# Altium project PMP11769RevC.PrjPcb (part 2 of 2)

## Sheet PMP11769RevC - Power Supply.SchDoc: Power Supply
size A3; Date: Not shown in title block; ApprovedBy: Not shown in title block; CheckedBy: Not shown in title block; Author: Not shown in title block; CompanyName: Not shown in title block; DrawnBy: Matthias Ulmann; Engineer: Matthias Ulmann; Organization: Not shown in title block; Address1: Not shown in title block; Address2: Not shown in title block; Address3: Not shown in title block; Address4: Not shown in title block; DocumentNumber: 4; Revision: Use project parameter SCH_Rev; SheetNumber: 4; SheetTotal: 4; PageSetup: Record=PageOptions¦CenterHorizontal=True¦CenterVertical=True¦PrintScale=0.96¦XCorrection=1.00¦YCorrection=1.00¦PrintKind=0¦BorderSize=5000000¦LeftOffset=0¦BottomOffset=0¦Orientation=2¦PaperLength=1000¦PaperWidth=1000¦Scale=100¦PaperSource=7¦PrintQuality=600¦MediaType=1¦DitherType=10¦PaperKind=11" x 17"¦PrintScaleMode=1
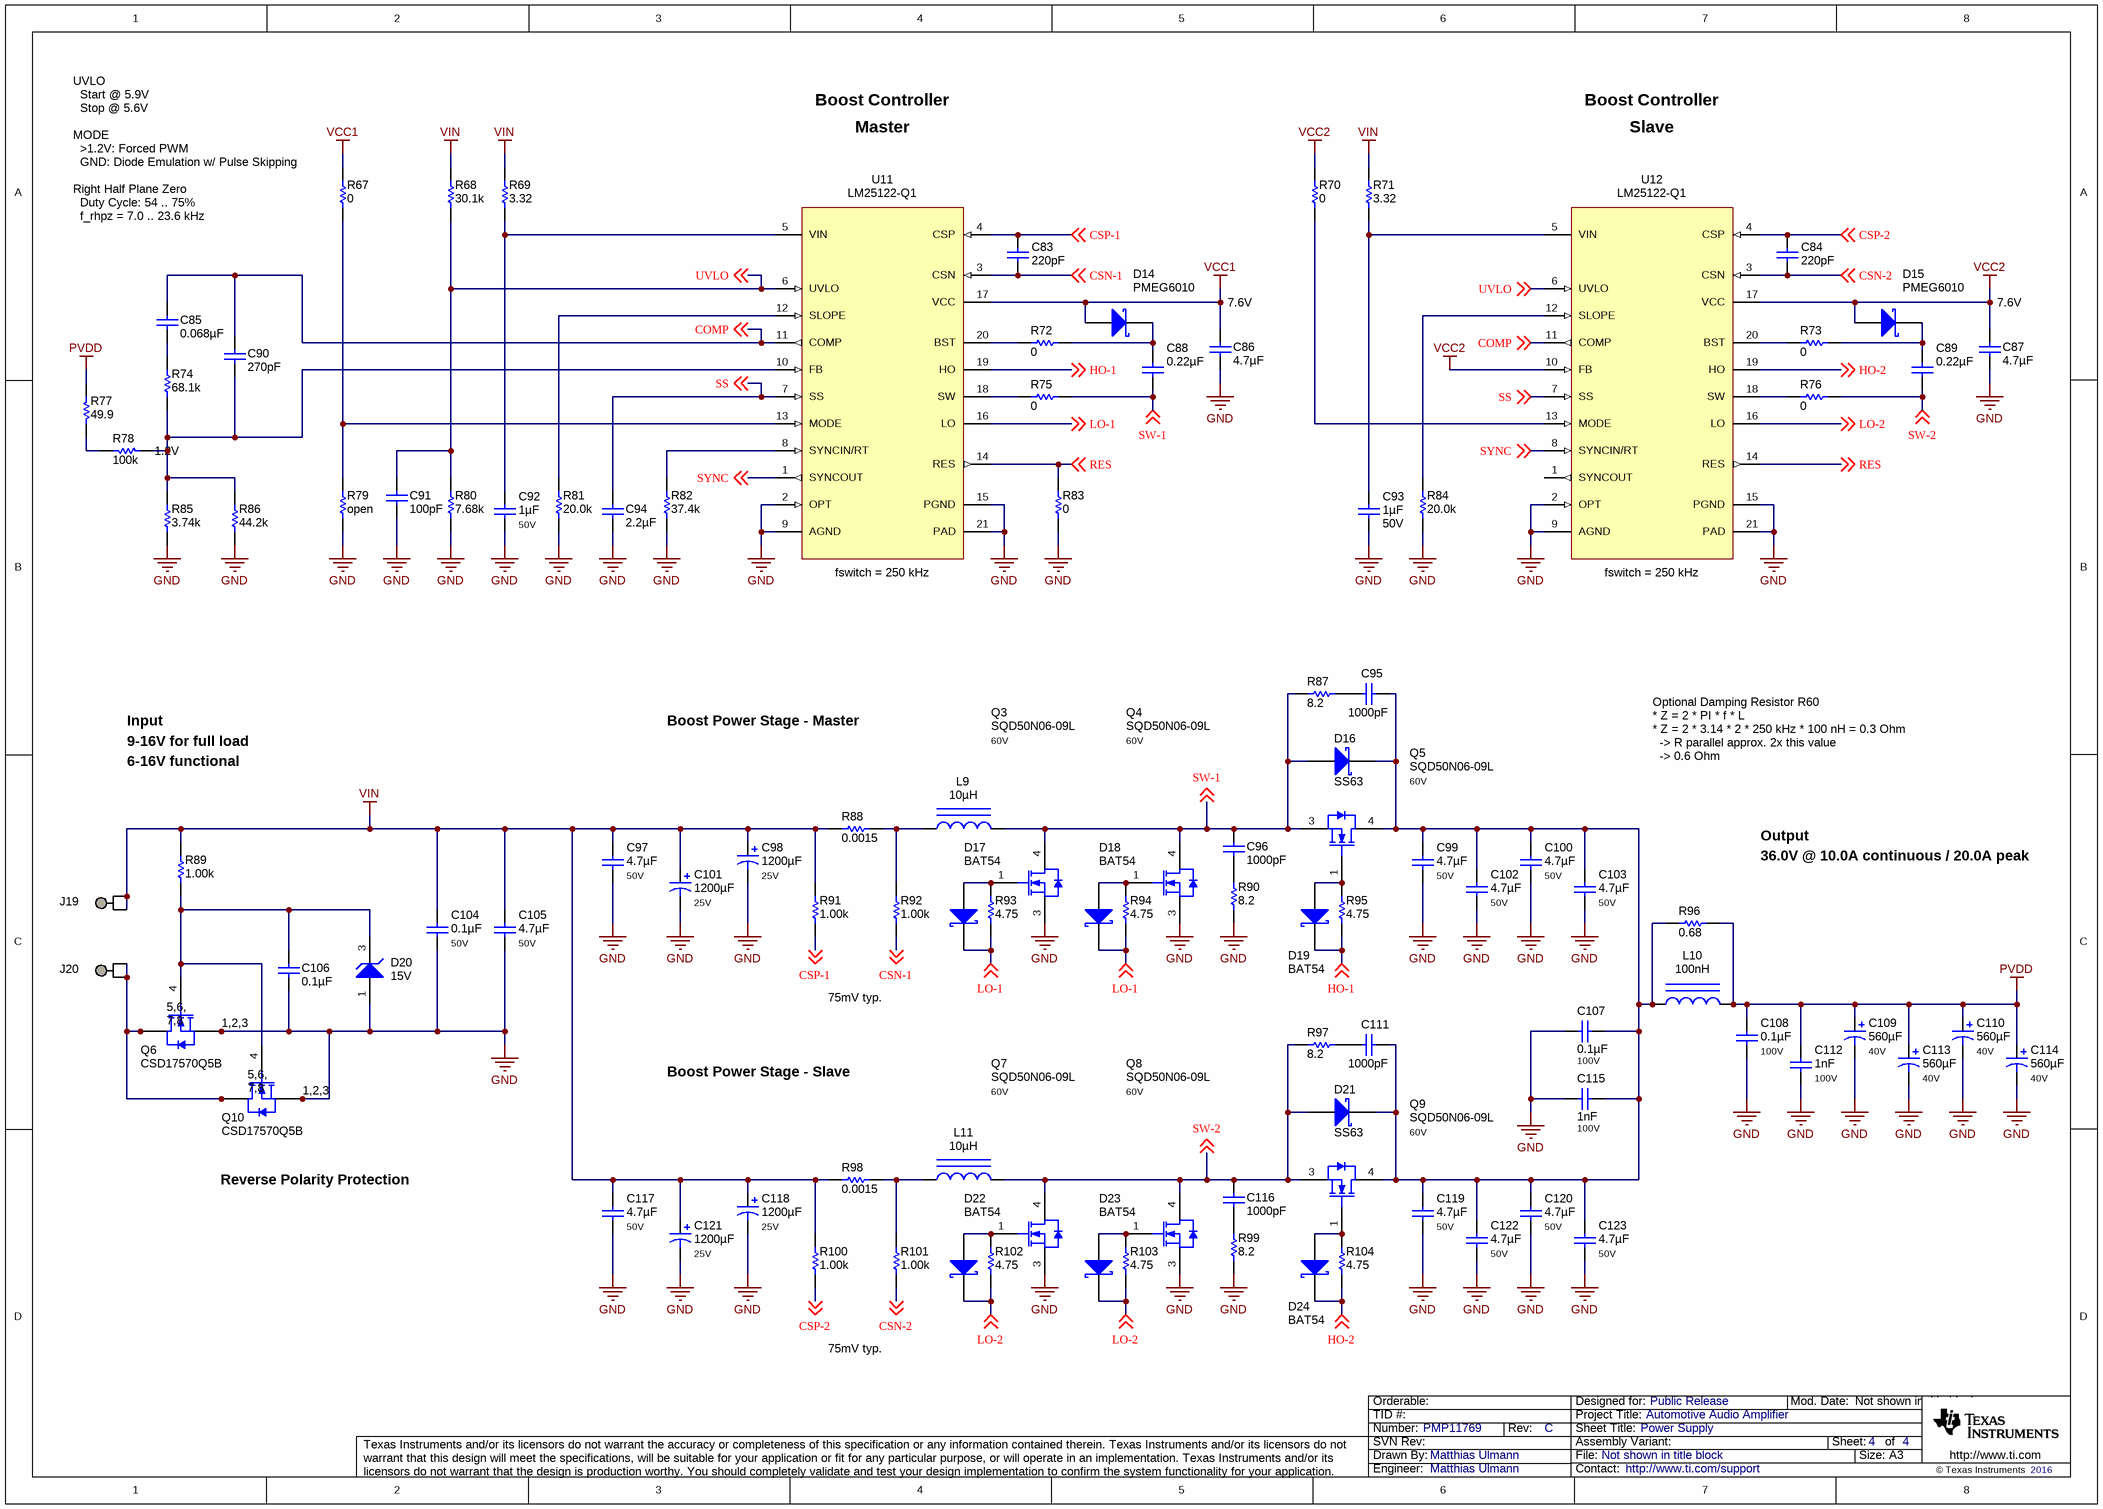
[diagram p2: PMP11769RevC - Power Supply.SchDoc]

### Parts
C83  ValueDisplayed: 220pF  [0603]  (hidden comment: C1608X7R1H221K)
C84  ValueDisplayed: 220pF  [0603]  (hidden comment: C1608X7R1H221K)
C85  ValueDisplayed: 0.068µF  [0603]  (hidden comment: C1608X7R1H683K080AA)
C86  ValueDisplayed: 4.7µF  [1206]  (hidden comment: C3216X7R1C475M)
C87  ValueDisplayed: 4.7µF  [1206]  (hidden comment: C3216X7R1C475M)
C88  ValueDisplayed: 0.22µF  [0805_HV]  (hidden comment: C2012X7R1E224K)
C89  ValueDisplayed: 0.22µF  [0805_HV]  (hidden comment: C2012X7R1E224K)
C90  ValueDisplayed: 270pF  [0603]  (hidden comment: GRM188R71H271KA01D)
C91  ValueDisplayed: 100pF  [0603]  (hidden comment: C1608C0G1H101J)
C92  ValueDisplayed: 1µF  Value2: 50V  [1206]  (hidden comment: C3216X7R1H105K)
C93  ValueDisplayed: 1µF  Value2: 50V  [1206]  (hidden comment: C3216X7R1H105K)
C94  ValueDisplayed: 2.2µF  [0603]  (hidden comment: GCM188R70J225KE22D)
C95  ValueDisplayed: 1000pF  [0805_HV]  (hidden comment: C2012X7R2A102M)
C96  ValueDisplayed: 1000pF  [0805_HV]  (hidden comment: C2012X7R2A102M)
C97  ValueDisplayed: 4.7µF  Value2: 50V  [1210]  (hidden comment: CGA6P3X7R1H475K250AB)
C98  ValueDisplayed: 1200µF  Value2: 25V  [PW_1800x2000]  (hidden comment: UPA1E122MHDANE)
C99  ValueDisplayed: 4.7µF  Value2: 50V  [1210]  (hidden comment: CGA6P3X7R1H475K250AB)
C100  ValueDisplayed: 4.7µF  Value2: 50V  [1210]  (hidden comment: CGA6P3X7R1H475K250AB)
C101  ValueDisplayed: 1200µF  Value2: 25V  [PW_1800x2000]  (hidden comment: UPA1E122MHDANE)
C102  ValueDisplayed: 4.7µF  Value2: 50V  [1210]  (hidden comment: CGA6P3X7R1H475K250AB)
C103  ValueDisplayed: 4.7µF  Value2: 50V  [1210]  (hidden comment: CGA6P3X7R1H475K250AB)
C104  ValueDisplayed: 0.1µF  Value2: 50V  [0603]  (hidden comment: C1608X7R1H104K)
C105  ValueDisplayed: 4.7µF  Value2: 50V  [1210]  (hidden comment: CGA6P3X7R1H475K250AB)
C106  ValueDisplayed: 0.1µF  [0603]  (hidden comment: C1608X7R1H104K)
C107  ValueDisplayed: 0.1µF  Value2: 100V  [0805_HV]  (hidden comment: C2012X7R2A104K125AA)
C108  ValueDisplayed: 0.1µF  Value2: 100V  [0805_HV]  (hidden comment: C2012X7R2A104K125AA)
C109  ValueDisplayed: 560µF  Value2: 40V  [PW_1800x2000]  (hidden comment: UPW1G561MHDANE)
C110  ValueDisplayed: 560µF  Value2: 40V  [PW_1800x2000]  (hidden comment: UPW1G561MHDANE)
C111  ValueDisplayed: 1000pF  [0805_HV]  (hidden comment: C2012X7R2A102M)
C112  ValueDisplayed: 1nF  Value2: 100V  [0805_HV]  (hidden comment: C2012X7R2A102M)
C113  ValueDisplayed: 560µF  Value2: 40V  [PW_1800x2000]  (hidden comment: UPW1G561MHDANE)
C114  ValueDisplayed: 560µF  Value2: 40V  [PW_1800x2000]  (hidden comment: UPW1G561MHDANE)
C115  ValueDisplayed: 1nF  Value2: 100V  [0805_HV]  (hidden comment: C2012X7R2A102M)
C116  ValueDisplayed: 1000pF  [0805_HV]  (hidden comment: C2012X7R2A102M)
C117  ValueDisplayed: 4.7µF  Value2: 50V  [1210]  (hidden comment: CGA6P3X7R1H475K250AB)
C118  ValueDisplayed: 1200µF  Value2: 25V  [PW_1800x2000]  (hidden comment: UPA1E122MHDANE)
C119  ValueDisplayed: 4.7µF  Value2: 50V  [1210]  (hidden comment: CGA6P3X7R1H475K250AB)
C120  ValueDisplayed: 4.7µF  Value2: 50V  [1210]  (hidden comment: CGA6P3X7R1H475K250AB)
C121  ValueDisplayed: 1200µF  Value2: 25V  [PW_1800x2000]  (hidden comment: UPA1E122MHDANE)
C122  ValueDisplayed: 4.7µF  Value2: 50V  [1210]  (hidden comment: CGA6P3X7R1H475K250AB)
C123  ValueDisplayed: 4.7µF  Value2: 50V  [1210]  (hidden comment: CGA6P3X7R1H475K250AB)
D14  PMEG6010  [SOD-123F]
D15  PMEG6010  [SOD-123F]
D16  SS63  [SMC]
D17  BAT54  [sod-323]
D18  BAT54  [sod-323]
D19  BAT54  [sod-323]
D20  value 15V  [SOT-23]  (hidden comment: BZX84C15LT1G)
D21  SS63  [SMC]
D22  BAT54  [sod-323]
D23  BAT54  [sod-323]
D24  BAT54  [sod-323]
J19  TESTPOINT_2Pos  [HIRSCHMANN_973 582-101]  (value not drawn)
J20  TESTPOINT_2Pos  [HIRSCHMANN_973 582-100]  (value not drawn)
L9  ValueDisplayed: 10µH  [SER2918H]  (hidden comment: SER2918H-103KL)
L10  100nH  [IHLP-2525AH]
L11  ValueDisplayed: 10µH  [SER2918H]  (hidden comment: SER2918H-103KL)
Q3  SQD50N06-09L  value 60V  [DPAK]
Q4  SQD50N06-09L  value 60V  [DPAK]
Q5  SQD50N06-09L  value 60V  [DPAK]
Q6  CSD17570Q5B  [TRANS_NexFET_Q5B]
Q7  SQD50N06-09L  value 60V  [DPAK]
Q8  SQD50N06-09L  value 60V  [DPAK]
Q9  SQD50N06-09L  value 60V  [DPAK]
Q10  CSD17570Q5B  [TRANS_NexFET_Q5B]
R67  ValueDisplayed: 0  [0603]  (hidden comment: CRCW06030000Z0EA)
R68  ValueDisplayed: 30.1k  [0603]  (hidden comment: CRCW060330K1FKEA)
R69  ValueDisplayed: 3.32  [0603]  (hidden comment: CRCW06033R32FKEA)
R70  ValueDisplayed: 0  [0603]  (hidden comment: CRCW06030000Z0EA)
R71  ValueDisplayed: 3.32  [0603]  (hidden comment: CRCW06033R32FKEA)
R72  ValueDisplayed: 0  [0603]  (hidden comment: CRCW06030000Z0EA)
R73  ValueDisplayed: 0  [0603]  (hidden comment: CRCW06030000Z0EA)
R74  ValueDisplayed: 68.1k  [0603]  (hidden comment: CRCW060368K1FKEA)
R75  ValueDisplayed: 0  [0603]  (hidden comment: CRCW06030000Z0EA)
R76  ValueDisplayed: 0  [0603]  (hidden comment: CRCW06030000Z0EA)
R77  ValueDisplayed: 49.9  [0603]  (hidden comment: CRCW060349R9FKEA)
R78  ValueDisplayed: 100k  [0603]  (hidden comment: CRCW0603100KFKEA)
R79  ValueDisplayed: open  [0603]  (hidden comment: CRCW06030000Z0EA)
R80  ValueDisplayed: 7.68k  [0603]  (hidden comment: CRCW06037K68FKEA)
R81  ValueDisplayed: 20.0k  [0603]  (hidden comment: CRCW060320K0FKEA)
R82  ValueDisplayed: 37.4k  [0603]  (hidden comment: CRCW060337K4FKEA)
R83  ValueDisplayed: 0  [0603]  (hidden comment: CRCW06030000Z0EA)
R84  ValueDisplayed: 20.0k  [0603]  (hidden comment: CRCW060320K0FKEA)
R85  ValueDisplayed: 3.74k  [0603]  (hidden comment: CRCW06033K74FKEA)
R86  ValueDisplayed: 44.2k  [0603]  (hidden comment: CRCW060344K2FKEA)
R87  ValueDisplayed: 8.2  [2010]  (hidden comment: CRCW20108R20JNEF)
R88  ValueDisplayed: 0.0015  [2512]  (hidden comment: ERJ-M1WTF1M5U)
R89  ValueDisplayed: 1.00k  [0603]  (hidden comment: CRCW06031K00FKEA)
R90  ValueDisplayed: 8.2  [2010]  (hidden comment: CRCW20108R20JNEF)
R91  ValueDisplayed: 1.00k  [0603]  (hidden comment: CRCW06031K00FKEA)
R92  ValueDisplayed: 1.00k  [0603]  (hidden comment: CRCW06031K00FKEA)
R93  ValueDisplayed: 4.75  [0603]  (hidden comment: CRCW06034R75FKEA)
R94  ValueDisplayed: 4.75  [0603]  (hidden comment: CRCW06034R75FKEA)
R95  ValueDisplayed: 4.75  [0603]  (hidden comment: CRCW06034R75FKEA)
R96  ValueDisplayed: 0.68  [2512]  (hidden comment: ERJ-1TRQJR68U)
R97  ValueDisplayed: 8.2  [2010]  (hidden comment: CRCW20108R20JNEF)
R98  ValueDisplayed: 0.0015  [2512]  (hidden comment: ERJ-M1WTF1M5U)
R99  ValueDisplayed: 8.2  [2010]  (hidden comment: CRCW20108R20JNEF)
R100  ValueDisplayed: 1.00k  [0603]  (hidden comment: CRCW06031K00FKEA)
R101  ValueDisplayed: 1.00k  [0603]  (hidden comment: CRCW06031K00FKEA)
R102  ValueDisplayed: 4.75  [0603]  (hidden comment: CRCW06034R75FKEA)
R103  ValueDisplayed: 4.75  [0603]  (hidden comment: CRCW06034R75FKEA)
R104  ValueDisplayed: 4.75  [0603]  (hidden comment: CRCW06034R75FKEA)
U11  LM25122-Q1  [PWP0020A_N]
U12  LM25122-Q1  [PWP0020A_N]

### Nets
GND: C86.2 C87.2 C91.2 C92.1 C93.1 C94.2 C97.2 C98.2(-) C99.2 C100.2 C101.2(-) C102.2 C103.2 C104.2 C105.2 C106.1 C107.1 C108.2 C109.2(-) C110.2(-) C112.2 C113.2(-) C114.2(-) C115.1 C117.2 C118.2(-) C119.2 C120.2 C121.2(-) C122.2 C123.2 D20.1(A) Q3.3(S) Q4.3(S) Q6.1(S) Q6.2(S) Q6.3(S) Q7.3(S) Q8.3(S) Q10.1(S) Q10.2(S) Q10.3(S) R79.2 R80.1 R81.1 R82.1 R83.1 R84.1 R85.1 R86.1 R90.1 R99.1 U11.2(OPT) U11.9(AGND) U11.15(PGND) U11.21(PAD) U12.2(OPT) U12.9(AGND) U12.15(PGND) U12.21(PAD)
PVDD: C108.1 C109.1(+) C110.1(+) C112.1 C113.1(+) C114.1(+) L10.2 R77.1 R96.2
VCC1: C86.1 D14.2(A) R67.1 U11.17(VCC)
VCC2: C87.1 D15.2(A) R70.1 U12.10(FB) U12.17(VCC)
VIN: C97.1 C98.1(+) C101.1(+) C104.1 C105.1 C117.1 C118.1(+) C121.1(+) J19.1 J19.2 R68.2 R69.2 R71.2 R88.1 R89.1 R91.2 R98.1 R100.2
COMP: C85.1 C90.1 U11.11(COMP) U12.11(COMP) ; off-sheet COMP
CSN-1: C83.2 R92.1 U11.3(CSN) ; off-sheet CSN-1
CSN-2: C84.2 R101.1 U12.3(CSN) ; off-sheet CSN-2
CSP-1: C83.1 R91.1 U11.4(CSP) ; off-sheet CSP-1
CSP-2: C84.1 R100.1 U12.4(CSP) ; off-sheet CSP-2
HO-1: D19.1(K) R95.1 U11.19(HO) ; off-sheet HO-1
HO-2: D24.1(K) R104.1 U12.19(HO) ; off-sheet HO-2
LO-1: D17.1(K) D18.1(K) R93.1 R94.1 U11.16(LO) ; off-sheet LO-1
LO-2: D22.1(K) D23.1(K) R102.1 R103.1 U12.16(LO) ; off-sheet LO-2
RES: R83.2 U11.14(RES) U12.14(RES) ; off-sheet RES
SS: C94.1 U11.7(SS) U12.7(SS) ; off-sheet SS
SW-1: C88.2 C96.1 D16.2(A) L9.1 Q3.4(D) Q4.4(D) Q5.3(S) R75.1 R87.1 ; off-sheet SW-1
SW-2: C89.2 C116.1 D21.2(A) L11.1 Q7.4(D) Q8.4(D) Q9.3(S) R76.1 R97.1 ; off-sheet SW-2
SYNC: U11.1(SYNCOUT) U12.8(SYNCIN/RT) ; off-sheet SYNC
UVLO: C91.1 R68.1 R80.2 U11.6(UVLO) U12.6(UVLO) ; off-sheet UVLO
NetC85_2: C85.2 R74.2
NetC88_1: C88.1 D14.1(K) R72.1
NetC89_1: C89.1 D15.1(K) R73.1
NetC90_2: C90.2 R74.1 R78.1 R85.2 R86.2 U11.10(FB)
NetC92_2: C92.2 R69.1 U11.5(VIN)
NetC93_2: C93.2 R71.1 U12.5(VIN)
NetC95_1: C95.1 R87.2
NetC95_2: C95.2 C99.1 C100.1 C102.1 C103.1 C107.2 C111.2 C115.2 C119.1 C120.1 C122.1 C123.1 D16.1(K) D21.1(K) L10.1 Q5.4(D) Q9.4(D) R96.1
NetC96_2: C96.2 R90.2
NetC106_2: C106.2 D20.3(K) Q6.4(G) Q10.4(G) R89.2
NetC111_1: C111.1 R97.2
NetC116_2: C116.2 R99.2
NetD17_2: D17.2(A) Q3.1(G) R93.2
NetD18_2: D18.2(A) Q4.1(G) R94.2
NetD19_2: D19.2(A) Q5.1(G) R95.2
NetD22_2: D22.2(A) Q7.1(G) R102.2
NetD23_2: D23.2(A) Q8.1(G) R103.2
NetD24_2: D24.2(A) Q9.1(G) R104.2
NetJ20_1: J20.1 J20.2 Q6.5(D) Q6.6(D) Q6.7(D) Q6.8(D) Q10.5(D) Q10.6(D) Q10.7(D) Q10.8(D)
NetL9_2: L9.2 R88.2 R92.2
NetL11_2: L11.2 R98.2 R101.2
NetR67_2: R67.2 R79.1 U11.13(MODE)
NetR70_2: R70.2 U12.13(MODE)
NetR72_2: R72.2 U11.20(BST)
NetR73_2: R73.2 U12.20(BST)
NetR75_2: R75.2 U11.18(SW)
NetR76_2: R76.2 U12.18(SW)
NetR77_2: R77.2 R78.2
NetR81_2: R81.2 U11.12(SLOPE)
NetR82_2: R82.2 U11.8(SYNCIN/RT)
NetR84_2: R84.2 U12.12(SLOPE)

Not connected (* = marked no-connect by the designer): U12 1(SYNCOUT)

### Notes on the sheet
- Boost Controller
- Master
- Slave
- (near R67) UVLO
  Start @ 5.9V
  Stop @ 5.6V
  MODE
  >1.2V: Forced PWM
  GND: Diode Emulation w/ Pulse Skipping
  Right Half Plane Zero
  Duty Cycle: 54 .. 75%
  f_rhpz = 7.0 .. 23.6 kHz
  Bandwidth < 700 Hz
- (near C86) 7.6V
- (near C87) 7.6V
- 1.2V
- (near U11) fswitch = 250 kHz
- (near U12) fswitch = 250 kHz
- Input
- Boost Power Stage - Master
- 9-16V for full load
- 6-16V functional
- Optional Damping Resistor R60
  * Z = 2 * PI * f * L
  * Z = 2 * 3.14 * 2 * 250 kHz * 100 nH = 0.3 Ohm
  -> R parallel approx. 2x this value
  -> 0.6 Ohm
- Output
- 36.0V @ 10.0A continuous / 20.0A peak
- 75mV typ.
- Boost Power Stage - Slave
- Reverse Polarity Protection

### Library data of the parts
C83 C84 = C1608X7R1H221K: CAP, CERM, 220 pF, 50 V, +/- 10%, X7R, 0603; Manufacturer: TDK; Polarized: N; CompType: Capacitor; Value: 220pF; U/M: EA; Cap_F: 0.00000000022; Tolerance_%: 10; Value1: Unknown; VDC_V: 50; Value2: 50V; TaMin_C: -55; TaMax_C: 125; AEC Category: Q200
C85 = C1608X7R1H683K080AA: CAP, CERM, 0.068 µF, 50 V, +/- 10%, X7R, 0603; Manufacturer: TDK; Polarized: N; CompType: Capacitor; Value: 0.068uF; U/M: EA; Cap_F: 0.000000068; Tolerance_%: 10; ESR_ohm: 0.035979; Value1: 0.035979 ohm; VDC_V: 50; Value2: 50V; IRMS_A: 0.886483; TaMin_C: -55; TaMax_C: 125; SizeArea_mm2: 1.28; SizeAreaWB_mm2: 4.68; SizeX_mm: 1.6; SizeY_mm: 0.8; SizeZ_mm: 1; AEC Category: Q200
C86 C87 = C3216X7R1C475M: CAP, CERM, 4.7 µF, 16 V, +/- 20%, X7R, 1206; Manufacturer: TDK; Polarized: N; CompType: Capacitor; Value: 4.7uF; U/M: EA; Cap_F: 0.0000047; Tolerance_%: 20; ESR_ohm: 0.0036; Value1: 0.0036 ohm; VDC_V: 16; Value2: 16V; IRMS_A: 2; TaMin_C: -55; TaMax_C: 125; AEC Category: Q200
C88 C89 = C2012X7R1E224K: CAP, CERM, 0.22 µF, 25 V, +/- 10%, X7R, 0805; Manufacturer: TDK; Polarized: N; CompType: Capacitor; Value: 0.22uF; U/M: EA; Cap_F: 0.00000022; Tolerance_%: 10; ESR_ohm: 0.0117; Value1: 0.0117 ohm; VDC_V: 25; Value2: 25V; TaMin_C: -55; TaMax_C: 125; Cap_Case: 0805; AEC Category: Q200
C90 = GRM188R71H271KA01D: CAP, CERM, 270 pF, 50 V, +/- 10%, X7R, 0603; Manufacturer: MuRata; Polarized: N; CompType: Capacitor; Value: 270pF; U/M: EA; Cap_F: 0.00000000027; Tolerance_%: 10; Value1: Unknown; VDC_V: 50; Value2: 50V; TaMin_C: -55; TaMax_C: 125; SizeArea_mm2: 1.28; SizeAreaWB_mm2: 4.68; SizeX_mm: 1.6; SizeY_mm: 0.8; SizeZ_mm: 1; AEC Category: Q200
C91 = C1608C0G1H101J: CAP, CERM, 100 pF, 50 V, +/- 5%, C0G/NP0, 0603; Manufacturer: TDK; Polarized: N; CompType: Capacitor; Value: 100pF; U/M: EA; Cap_F: 0.0000000001; Tolerance_%: 5; ESR_ohm: 0.1679; Value1: 0.1679 ohm; VDC_V: 50; Value2: 50V; TaMin_C: -55; TaMax_C: 125; AEC Category: Q200
C92 C93 = C3216X7R1H105K: CAP, CERM, 1 µF, 50 V, +/- 10%, X7R, 1206; Manufacturer: TDK; Polarized: N; CompType: Capacitor; Value: 1uF; U/M: EA; Cap_F: 0.000001; Tolerance_%: 10; ESR_ohm: 0.01; Value1: 0.01 ohm; VDC_V: 50; IRMS_A: 3.2; TaMin_C: -55; TaMax_C: 125; AEC Category: Q200
C94 = GCM188R70J225KE22D: CAP, CERM, 2.2 µF, 6.3 V, +/- 10%, X7R, AEC-Q200 Grade 1, 0603; Manufacturer: MuRata; Polarized: N; CompType: Capacitor; Value: 2.2uF; U/M: EA; Cap_F: 0.0000022; Tolerance_%: 10; Value1: Unknown; VDC_V: 6.3; Value2: 6.3V; TaMin_C: -55; TaMax_C: 125; AEC Category: Q200; AEC Qualified: Y; AEC Grade: 1
C95 C96 C111 C116 = C2012X7R2A102M: CAP, CERM, 1000 pF, 100 V, +/- 20%, X7R, 0805; Manufacturer: TDK; Polarized: N; CompType: Capacitor; Value: 1000pF; U/M: EA; Cap_F: 0.000000001; Tolerance_%: 20; ESR_ohm: 0.281; Value1: 0.281 ohm; VDC_V: 100; Value2: 100V; TaMin_C: -55; TaMax_C: 125; Cap_Case: 0805; AEC Category: Q200
C97 C99 C100 C102 C103 C105 C117 C119 C120 C122 C123 = C3225X7R1H335M: CAP, CERM, 4.7 µF, 50 V, +/- 15%, X7R, 1210; Manufacturer: TDK; Polarized: N; CompType: Capacitor; Value: 4.7uF; U/M: EA; Cap_F: 0.0000033; Tolerance_%: 15; Value1: Unknown; VDC_V: 50; TaMin_C: -55; TaMax_C: 125
C98 C101 C118 C121 = UPW1V182MHD6: CAP, AL, 1200 µF, 25 V, +/- 20%, 0.036 ohm, TH; Manufacturer: Nichicon; Polarized: Y; CompType: Capacitor; Value: 1200uF; U/M: EA; Cap_F: 0.0012; Tolerance_%: 20; VDC_V: 25; ESR_ohm: 0.036; IRMS_A: 2.2; TaMin_C: -55; TaMax_C: 105; Cap_Case: 18x15mm; AEC Category: Q200; AEC Qualified: N
C104 = C1608X7R1H104K: CAP, CERM, 0.1 µF, 50 V, +/- 10%, X7R, 0603; Manufacturer: TDK; Polarized: N; CompType: Capacitor; Value: 0.1uF; U/M: EA; Cap_F: 0.0000001; Tolerance_%: 10; ESR_ohm: 0.017; Value1: 0.017 ohm; VDC_V: 50; TaMin_C: -55; TaMax_C: 125; AEC Category: Q200
C106 = C1608X7R1H104K: CAP, CERM, 0.1 µF, 50 V, +/- 10%, X7R, 0603; Manufacturer: TDK; Polarized: N; CompType: Capacitor; Value: 0.1uF; U/M: EA; Cap_F: 0.0000001; Tolerance_%: 10; ESR_ohm: 0.017; Value1: 0.017 ohm; VDC_V: 50; Value2: 50V; TaMin_C: -55; TaMax_C: 125; AEC Category: Q200
C107 C108 = C2012X7R2A104K125AA: CAP, CERM, 0.1 µF, 100 V, +/- 10%, X7R, 0805; Manufacturer: TDK; Polarized: N; CompType: Capacitor; Value: 0.1uF; U/M: EA; Cap_F: 0.0000001; Tolerance_%: 10; ESR_ohm: 0.0158; Value1: 0.0158 ohm; VDC_V: 100; TaMin_C: -55; TaMax_C: 125; Cap_Case: 0805; AEC Category: Q200
C109 C110 C113 C114 = UPW1H821MHD6: CAP, AL, 560 µF, 40 V, +/- 20%, 0.045 ohm, TH; Manufacturer: Nichicon; Polarized: Y; CompType: Capacitor; Value: 560uF; U/M: EA; Cap_F: 0.00056; Tolerance_%: 20; VDC_V: 40; ESR_ohm: 0.045; IRMS_A: 2.0; TaMin_C: -55; TaMax_C: 105; Cap_Case: 18x15mm; AEC Category: Q200; AEC Qualified: N
C112 C115 = C2012X7R2A102M: CAP, CERM, 1000 pF, 100 V, +/- 20%, X7R, 0805; Manufacturer: TDK; Polarized: N; CompType: Capacitor; Value: 1000pF; U/M: EA; Cap_F: 0.000000001; Tolerance_%: 20; ESR_ohm: 0.281; Value1: 0.281 ohm; VDC_V: 100; TaMin_C: -55; TaMax_C: 125; Cap_Case: 0805; AEC Category: Q200
D14 D15 = PMEG6010CEH,115: Diode, Schottky, 60 V, 1 A, SOD-123F; Manufacturer: NXP Semiconductor; U/M: EA; Vf_V: 0.57; Value: 60V; Value1: 1A; Value2: 0.57V; Io_A: 1; Vr_V: 60; TJmax_C: 150; AEC Category: Q101
D16 D21 = SS36-E3/57T: Diode, Schottky, 60 V, 3 A, SMC; Manufacturer: Vishay-Semiconductor; U/M: EA; Vf_V: 0.75; Value: 60V; Value1: 3A; Value2: 0.75V; Io_A: 3; Vr_V: 60; TJmax_C: 150; RJC_CperW: 17; AEC Category: Q101
D17-D19 D22-D24 = BAT54HT1G: Diode, Schottky, 30 V, 0.2 A, SOD-323; Manufacturer: ON Semiconductor; U/M: EA; Vf_V: 0.35; Value: 30V; Value1: 0.2A; Value2: 0.35V; Io_A: 0.2; Vr_V: 30; AEC Category: Q101
D20 = BZX84C15LT1G: Diode, Zener, 15 V, 225 mW, SOT-23; Manufacturer: ON Semiconductor; U/M: EA; Power_W: 0.225; Vz_V: 15; Value1: 0.225W; RJA_CperW: 556; AEC Category: Q101
J19 = 973 582-101: TEST SOCKET, PCB, 4MM, RED; Manufacturer: Hirschmann; SymbolCreator: a0799628
J20 = 973 582-100: TEST SOCKET, PCB, 4MM, BLACK; Manufacturer: Hirschmann; SymbolCreator: a0799628
L9 L11 = SER2918H-103KL: Inductor, Shielded E Core, Ferrite, 10 µH, 28 A, 0.0026 ohm, SMD; Manufacturer: Coilcraft; Value: 10uH; Ind_H: 10.0E-6; Imax_A: 28; Irms: 28A @ 40C rise; Isat: 32.1A @ 30% inductance drop; DCR_ohm: 0.0026; Value2: 28A; AEC Category: Q200
L10 = IHLP2525AHERR10M01: Inductor, Shielded, Ferrite, 100 nH, 18 A, 0.0035 ohm, SMD; Manufacturer: Vishay-Dale; Ind_H: 100.0E-9; Imax_A: 18; Irms: 18A @ 40C rise; Isat: 40A @ 20% inductance drop; DCR_ohm: 0.0035; Value2: 18A
Q3-Q5 Q7-Q9 = SUD50N10-18P: MOSFET, N-CH, 60 V, 50 A, DPAK; Manufacturer: Vishay-Siliconix; Alternate Manufacturer: None; U/M: EA; ChType: N; VdsMax_V: 60; QgTyp_nC: 48; Vgs_V: 20; IdsMax_A: 50; AEC Category: Q101
Q6 Q10 = CSD17570Q5B: MOSFET, N-CH, 30 V, 51 A, SON 5x6mm; Manufacturer: Texas Instruments; Alternate Manufacturer: None; U/M: EA; ChType: N; Value: 30V; VdsMax_V: 30; Value1: 0.0076 ohm; Rdson45_ohm: 0.0076; Value2: 97 nC; QgTyp_nC: 97; Vgs_V: 20; IdsMax_A: 51; AEC Category: Q101
R67 R70 R72 R73 R75 R76 R79 R83 = CRCW06030000Z0EA: RES, 0, 5%, 0.1 W, 0603; Manufacturer: Vishay-Dale; CompType: Resistor; Value: 0; Value_Code: 0000; Tolerance_%: 5; Power_W: 0.1; Value2: 0.1W; VDC_V: 75; TempCo: 200 ppm/C; EIA_Code: E24; U/M: EA; AEC Category: Q200
R68 = CRCW060330K1FKEA: RES, 30.1 k, 1%, 0.1 W, 0603; Manufacturer: Vishay-Dale; CompType: Resistor; Value: 30.1k; Res_ohm: 30100; Value_Code: 30k1; Tolerance_%: 1; Power_W: 0.1; Value2: 0.1W; VDC_V: 75; TempCo: 100 ppm/C; EIA_Code: E96; U/M: EA; AEC Category: Q200
R69 R71 = CRCW06033R32FKEA: RES, 3.32, 1%, 0.1 W, 0603; Manufacturer: Vishay-Dale; CompType: Resistor; Value: 3.32; Value_Code: 3R32; Tolerance_%: 1; Power_W: 0.1; Value2: 0.1W; VDC_V: 75; TempCo: 100 ppm/C; EIA_Code: E96; U/M: EA; AEC Category: Q200
R74 = CRCW060368K1FKEA: RES, 68.1 k, 1%, 0.1 W, 0603; Manufacturer: Vishay-Dale; CompType: Resistor; Value: 68.1k; Res_ohm: 68100; Value_Code: 68k1; Tolerance_%: 1; Power_W: 0.1; Value2: 0.1W; VDC_V: 75; TempCo: 100 ppm/C; SizeArea_mm2: 1.28; SizeX_mm: 1.6; SizeY_mm: 0.8; EIA_Code: E96; U/M: EA; AEC Category: Q200
R77 = CRCW060349R9FKEA: RES, 49.9, 1%, 0.1 W, 0603; Manufacturer: Vishay-Dale; CompType: Resistor; Value: 49.9; Value_Code: 49R9; Tolerance_%: 1; Power_W: 0.1; Value2: 0.1W; VDC_V: 75; TempCo: 100 ppm/C; EIA_Code: E96; U/M: EA; AEC Category: Q200
R78 = CRCW0603100KFKEA: RES, 100 k, 1%, 0.1 W, 0603; Manufacturer: Vishay-Dale; CompType: Resistor; Value: 100k; Res_ohm: 100000; Tolerance_%: 1; Power_W: 0.1; Value2: 0.1W; VDC_V: 75; TempCo: 100 ppm/C; EIA_Code: E96; U/M: EA; AEC Category: Q200
R80 = CRCW06037K68FKEA: RES, 7.68 k, 1%, 0.1 W, 0603; Manufacturer: Vishay-Dale; CompType: Resistor; Value: 7.68k; Res_ohm: 7680; Value_Code: 7k68; Tolerance_%: 1; Power_W: 0.1; Value2: 0.1W; VDC_V: 75; TempCo: 100 ppm/C; EIA_Code: E96; U/M: EA; AEC Category: Q200
R81 R84 = CRCW060320K0FKEA: RES, 20.0 k, 1%, 0.1 W, 0603; Manufacturer: Vishay-Dale; CompType: Resistor; Value: 20.0k; Res_ohm: 20000; Value_Code: 20k0; Tolerance_%: 1; Power_W: 0.1; Value2: 0.1W; VDC_V: 75; TempCo: 100 ppm/C; EIA_Code: E96; U/M: EA; AEC Category: Q200
R82 = CRCW060337K4FKEA: RES, 37.4 k, 1%, 0.1 W, 0603; Manufacturer: Vishay-Dale; CompType: Resistor; Value: 37.4k; Res_ohm: 37400; Value_Code: 37k4; Tolerance_%: 1; Power_W: 0.1; Value2: 0.1W; VDC_V: 75; TempCo: 100 ppm/C; EIA_Code: E96; U/M: EA; AEC Category: Q200
R85 = CRCW06033K74FKEA: RES, 3.74 k, 1%, 0.1 W, 0603; Manufacturer: Vishay-Dale; CompType: Resistor; Value: 3.74k; Res_ohm: 3740; Value_Code: 3k74; Tolerance_%: 1; Power_W: 0.1; Value2: 0.1W; VDC_V: 75; TempCo: 100 ppm/C; EIA_Code: E96; U/M: EA; AEC Category: Q200
R86 = CRCW060344K2FKEA: RES, 44.2 k, 1%, 0.1 W, 0603; Manufacturer: Vishay-Dale; CompType: Resistor; Value: 44.2k; Res_ohm: 44200; Value_Code: 44k2; Tolerance_%: 1; Power_W: 0.1; Value2: 0.1W; VDC_V: 75; TempCo: 100 ppm/C; EIA_Code: E96; U/M: EA; AEC Category: Q200
R87 R90 R97 R99 = CRCW20108R20JNEF: RES, 8.2, 5%, 0.75 W, 2010; Manufacturer: Vishay-Dale; CompType: Resistor; Value: 8.2; Value_Code: 8R20; Tolerance_%: 5; Power_W: 0.75; Value2: 0.75W; VDC_V: 400; TempCo: 200 ppm/C; EIA_Code: E24; U/M: EA; AEC Category: Q200
R88 R98 = ERJ-M1WTF1M5U: RES, 0.0015, 1%, 1 W, 2512; Manufacturer: Panasonic; CompType: Resistor; Value: 0.0015; Value_Code: 1L500; Tolerance_%: 1; Value2: 1W; TempCo: ppm/C; U/M: EA; AEC Category: Q200
R89 R91 R92 R100 R101 = CRCW06031K00FKEA: RES, 1.00 k, 1%, 0.1 W, 0603; Manufacturer: Vishay-Dale; CompType: Resistor; Value: 1.00k; Res_ohm: 1000; Value_Code: 1k00; Tolerance_%: 1; Power_W: 0.1; Value2: 0.1W; VDC_V: 75; TempCo: 100 ppm/C; EIA_Code: E96; U/M: EA; AEC Category: Q200
R93-R95 R102-R104 = CRCW06034R75FKEA: RES, 4.75, 1%, 0.1 W, 0603; Manufacturer: Vishay-Dale; CompType: Resistor; Value: 4.75; Value_Code: 4R75; Tolerance_%: 1; Power_W: 0.1; Value2: 0.1W; VDC_V: 75; TempCo: 100 ppm/C; EIA_Code: E96; U/M: EA; AEC Category: Q200
R96 = ERJ-1TRQJR68U: RES, 0.68, 5%, 1 W, 2512; Manufacturer: Panasonic; CompType: Resistor; Value: 0.68; Value_Code: R680; Tolerance_%: 5; Power_W: 1; Value2: 1W; TempCo: 200 ppm/C; U/M: EA; AEC Category: Q200
U11 U12 = LM5122QMHX/NOPB: Wide Input Synchronous Boost Controller with Multiple Phase Capability, PWP0020A; PartNumber: LM25122QMHX/NOPB; Alternate PartNumber: LM25122QMHE/NOPB; Manufacturer: Texas Instruments; Alternate Manufacturer: None; SymbolCreator: a0411947; CompType: IC; U/M: EA

## Sheet PMP11769Revc - Clipping Detector.SchDoc: Clipping Detector
size A3; Date: Not shown in title block; ApprovedBy: Not shown in title block; CheckedBy: Not shown in title block; Author: Not shown in title block; CompanyName: Not shown in title block; DrawnBy: Matthias Ulmann; Engineer: Not shown in title block; Organization: Not shown in title block; Address1: Not shown in title block; Address2: Not shown in title block; Address3: Not shown in title block; Address4: Not shown in title block; DocumentNumber: 3; Revision: Use project parameter SCH_Rev; SheetNumber: 3; SheetTotal: 4; PageSetup: Record=PageOptions¦CenterHorizontal=True¦CenterVertical=True¦PrintScale=1.00¦XCorrection=1.00¦YCorrection=1.00¦PrintKind=0¦BorderSize=5000000¦LeftOffset=0¦BottomOffset=0¦Orientation=2¦PaperLength=1000¦PaperWidth=1000¦Scale=100¦PaperSource=15¦PrintQuality=600¦MediaType=1¦DitherType=10¦PaperKind=Letter¦PrintScaleMode=1
Used 2 times, as channels 1, 2. Parts and nets are listed once, with the designators drawn on the sheet.
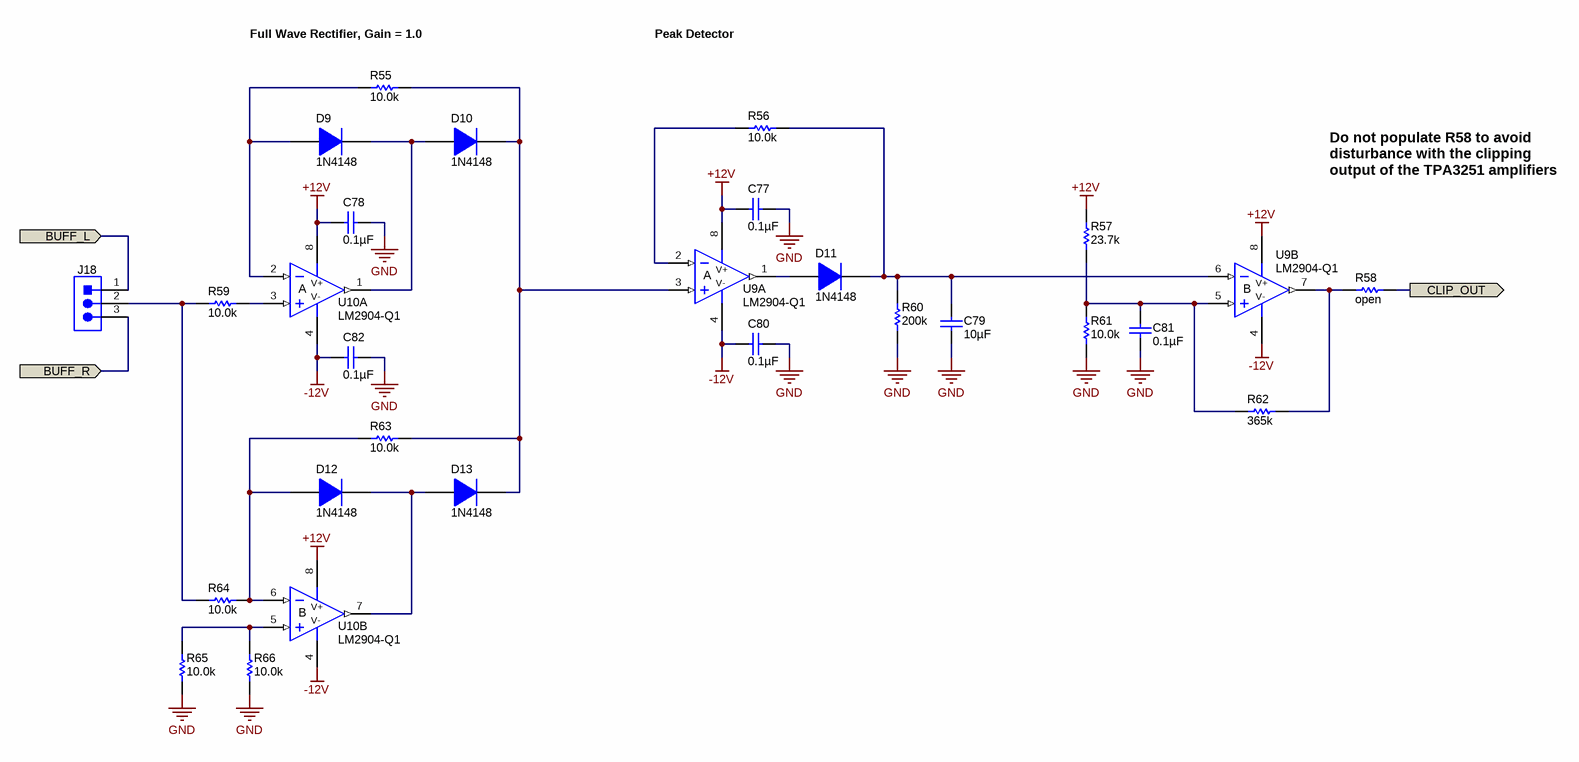
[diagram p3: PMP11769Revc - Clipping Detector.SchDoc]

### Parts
C77  ValueDisplayed: 0.1µF  [0603]  (hidden comment: C1608X7R1H104K)
C78  ValueDisplayed: 0.1µF  [0603]  (hidden comment: C1608X7R1H104K)
C79  ValueDisplayed: 10µF  [1210]  (hidden comment: C3225X7R1E106M)
C80  ValueDisplayed: 0.1µF  [0603]  (hidden comment: C1608X7R1H104K)
C81  ValueDisplayed: 0.1µF  [0603]  (hidden comment: C1608X7R1H104K)
C82  ValueDisplayed: 0.1µF  [0603]  (hidden comment: C1608X7R1H104K)
D9  1N4148  [SOD-123FL]
D10  1N4148  [SOD-123FL]
D11  1N4148  [SOD-123FL]
D12  1N4148  [SOD-123FL]
D13  1N4148  [SOD-123FL]
J18  61300311121  [WURTH_61300311121]  (value not drawn)
R55  ValueDisplayed: 10.0k  [0603]  (hidden comment: CRCW060310K0FKEA)
R56  ValueDisplayed: 10.0k  [0603]  (hidden comment: CRCW060310K0FKEA)
R57  ValueDisplayed: 23.7k  [0603]  (hidden comment: CRCW060323K7FKEA)
R58  ValueDisplayed: open  [0603]  (hidden comment: CRCW06031K00FKEA)
R59  ValueDisplayed: 10.0k  [0603]  (hidden comment: CRCW060310K0FKEA)
R60  ValueDisplayed: 200k  [0603]  (hidden comment: CRCW0603200KFKEA)
R61  ValueDisplayed: 10.0k  [0603]  (hidden comment: CRCW060310K0FKEA)
R62  ValueDisplayed: 365k  [0603]  (hidden comment: CRCW0603365KFKEA)
R63  ValueDisplayed: 10.0k  [0603]  (hidden comment: CRCW060310K0FKEA)
R64  ValueDisplayed: 10.0k  [0603]  (hidden comment: CRCW060310K0FKEA)
R65  ValueDisplayed: 10.0k  [0603]  (hidden comment: CRCW060310K0FKEA)
R66  ValueDisplayed: 10.0k  [0603]  (hidden comment: CRCW060310K0FKEA)
U9  LM2904-Q1  [D0008A_N]  (parts A,B of 2)
U10  LM2904-Q1  [D0008A_N]  (parts A,B of 2)

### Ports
BUFF_L, BUFF_R, CLIP_OUT (out)

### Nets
+12V: C77.1 C78.1 R57.2 U9.8(V+) U10.8(V+)
-12V: C80.1 C82.1 U9.4(V-) U10.4(V-)
GND: C77.2 C78.2 C79.2 C80.2 C81.1 C82.2 R60.1 R61.2 R65.1 R66.1
BUFF_L: J18.1 ; port BUFF_L
BUFF_R: J18.3 ; port BUFF_R
CLIP_OUT: R58.2 ; port CLIP_OUT
NetC79_1: C79.1 D11.1(K) R56.1 R60.2 U9.6(IN-)
NetC81_2: C81.2 R57.1 R61.1 R62.1 U9.5(IN+)
NetD9_1: D9.1(K) D10.2(A) U10.1(OUT)
NetD9_2: D9.2(A) R55.2 U10.2(IN-)
NetD10_1: D10.1(K) D13.1(K) R55.1 R63.1 U9.3(IN+)
NetD11_2: D11.2(A) U9.1(OUT)
NetD12_1: D12.1(K) D13.2(A) U10.7(OUT)
NetD12_2: D12.2(A) R63.2 R64.2 U10.6(IN-)
NetJ18_2: J18.2 R59.1 R64.1
NetR56_2: R56.2 U9.2(IN-)
NetR58_1: R58.1 R62.2 U9.7(OUT)
NetR59_2: R59.2 U10.3(IN+)
NetR65_2: R65.2 R66.2 U10.5(IN+)

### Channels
1: designators end in _1; ports BUFF_L=BUFF_L1 BUFF_R=BUFF_R1 CLIP_OUT=/CLIP
2: designators end in _2; ports BUFF_L=BUFF_L2 BUFF_R=BUFF_R2 CLIP_OUT=/CLIP

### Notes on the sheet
- (near R55) Full Wave Rectifier, Gain = 1.0
- Peak Detector
- Do not populate R58 to avoid
  disturbance with the clipping
  output of the TPA3251 amplifiers

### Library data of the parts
C77 C78 C80-C82 = C1608X7R1H104K: as C106 on sheet PMP11769RevC - Power Supply
C79 = C3225X7R1E106M: CAP, CERM, 10 µF, 25 V, +/- 20%, X7R, 1210; Manufacturer: TDK; Polarized: N; CompType: Capacitor; Value: 10uF; U/M: EA; Cap_F: 0.00001; Tolerance_%: 20; ESR_ohm: 0.0027; Value1: 0.0027 ohm; VDC_V: 25; Value2: 25V; IRMS_A: 3; TaMin_C: -55; TaMax_C: 125; AEC Category: Q200
D9-D13 = 1N4148WFL-G3-08: Diode, Switching, 100 V, 0.15 A, SOD-123FL; Manufacturer: Vishay-Semiconductor; U/M: EA; Vf_V: 1.2; Value: 100V; Value1: 0.15A; Value2: 1.2V; Io_A: 0.15; Vr_V: 100; TJmax_C: 150; AEC Category: Q101
J18 = 61300311121: Header, 2.54 mm, 3x1, Gold, TH; Manufacturer: Wurth Elektronik; SymbolCreator: a0799628
R55 R56 R59 R61 R63-R66 = CRCW060310K0FKEA: RES, 10.0 k, 1%, 0.1 W, 0603; Manufacturer: Vishay-Dale; CompType: Resistor; Value: 10.0k; Res_ohm: 10000; Value_Code: 10k0; Tolerance_%: 1; Power_W: 0.1; Value2: 0.1W; VDC_V: 75; TempCo: 100 ppm/C; EIA_Code: E96; U/M: EA; AEC Category: Q200
R57 = CRCW060323K7FKEA: RES, 23.7 k, 1%, 0.1 W, 0603; Manufacturer: Vishay-Dale; CompType: Resistor; Value: 23.7k; Res_ohm: 23700; Value_Code: 23k7; Tolerance_%: 1; Power_W: 0.1; Value2: 0.1W; VDC_V: 75; TempCo: 100 ppm/C; EIA_Code: E96; U/M: EA; AEC Category: Q200
R58 = CRCW06031K00FKEA: as R89 on sheet PMP11769RevC - Power Supply
R60 = CRCW0603200KFKEA: RES, 200 k, 1%, 0.1 W, 0603; Manufacturer: Vishay-Dale; CompType: Resistor; Value: 200k; Res_ohm: 200000; Tolerance_%: 1; Power_W: 0.1; Value2: 0.1W; VDC_V: 75; TempCo: 100 ppm/C; EIA_Code: E96; U/M: EA; AEC Category: Q200
R62 = CRCW0603365KFKEA: RES, 365 k, 1%, 0.1 W, 0603; Manufacturer: Vishay-Dale; CompType: Resistor; Value: 365k; Res_ohm: 365000; Tolerance_%: 1; Power_W: 0.1; Value2: 0.1W; VDC_V: 75; TempCo: 100 ppm/C; EIA_Code: E96; U/M: EA; AEC Category: Q200
U9 U10 = LM2904QDRQ1: Automotive Dual Low Power Op Amp, D0008A; Manufacturer: Texas Instruments; CompType: OpAmp IC

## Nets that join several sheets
+3V3: PMP11769RevC - System (8 pins), 1 (J17_1.1 R54_1.1), 2 (J17_2.1 R54_2.1)
+12V: PMP11769RevC - System (10 pins), 1 (9 pins), 2 (9 pins), 1 (5 pins), 2 (5 pins)
-12V: PMP11769RevC - System (C11.2 L4.2 R14.2 R16.2), 1 (6 pins), 2 (6 pins), 1 (C80_1.1 C82_1.1 U9_1.4 U10_1.4), 2 (C80_2.1 C82_2.1 U9_2.4 U10_2.4)
GND: PMP11769RevC - System (31 pins), 1 (71 pins), 2 (71 pins), PMP11769RevC - Power Supply (60 pins), 1 (10 pins), 2 (10 pins)
PVDD: PMP11769RevC - System (7 pins), 1 (18 pins), 2 (18 pins), PMP11769RevC - Power Supply (9 pins)
/CLIP: PMP11769RevC - System (Q2.1 R7.1), 1 (U8_1.21), 2 (U8_2.21), 1 (R58_1.2), 2 (R58_2.2)
/FAULT: PMP11769RevC - System (R1.1 R4.1), 1 (U8_1.19), 2 (U8_2.19)
/RESET: PMP11769RevC - System (C1.1 R3.1 S1.2 U1.3), 1 (U8_1.18), 2 (U8_2.18)
BUFF_L1: 1 (J6_1.1 R28_1.1 R31_1.2 U5_1.1), 1 (J18_1.1)
BUFF_L2: 2 (J6_2.1 R28_2.1 R31_2.2 U5_2.1), 2 (J18_2.1)
BUFF_R1: 1 (J7_1.1 R33_1.1 R44_1.2 U5_1.7), 1 (J18_1.3)
BUFF_R2: 2 (J7_2.1 R33_2.1 R44_2.2 U5_2.7), 2 (J18_2.3)
IN_L1: PMP11769RevC - System (J3.1), 1 (J5_1.3 R20_1.1)
IN_L2: PMP11769RevC - System (J3.2), 2 (J5_2.3 R20_2.1)
IN_R1: PMP11769RevC - System (J1.1), 1 (J8_1.3 R37_1.1)
IN_R2: PMP11769RevC - System (J1.2), 2 (J8_2.3 R37_2.1)
OSC_IOM1: PMP11769RevC - System (J2.2 J4.1), 1 (U8_1.9)
OSC_IOM2: PMP11769RevC - System (J2.1), 2 (U8_2.9)
OSC_IOP1: PMP11769RevC - System (J4.2), 1 (U8_1.10)
OSC_IOP2: PMP11769RevC - System (J2.3 J4.3), 2 (U8_2.10)

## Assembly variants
001: all parts fitted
